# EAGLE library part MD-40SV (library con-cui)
MINI CIRCULAR CON. - VERTICAL MOUNT Source: http://cui.com/pdffiles/MD-40SV.pdf
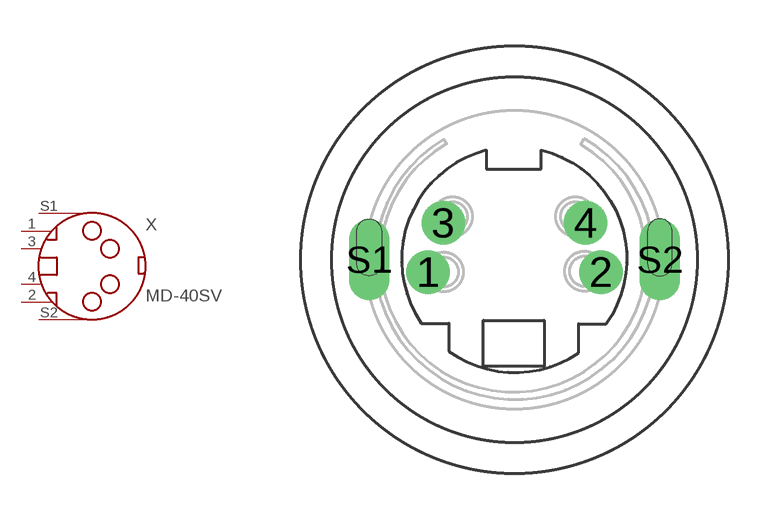
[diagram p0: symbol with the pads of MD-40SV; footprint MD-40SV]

Designator prefix X

## MD-40SV (OC_FARNELL: unknown; OC_NEWARK: unknown)  [MD-40SV]
1  1  pas
2  2  pas
3  3  pas
4  4  pas
S1  S  pas
S2  S  pas

## Footprint MD-40SV (pad centres in mm)
MINI CIRCULAR CON. - VERTICAL MOUNT Source: http://cui.com/pdffiles/MD-40SV.pdf
drill 0.9 pad 1.27 round: 1 -2.8,-0.4; 2 2.8,-0.4; 3 -2.3,1.2; 4 2.3,1.2
drill 0.8 pad 1.27 long: S1 -4.7,0; S2 4.7,0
